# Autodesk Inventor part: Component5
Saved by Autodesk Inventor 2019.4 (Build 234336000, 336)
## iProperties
Created: 2020-06
Part Number: Component5
Material: Generic
Document SubType Name: Modeling
Designer: Administrator
Density: 1 g/cm^3
Appearance: Default
Title: Component5
Author: Administrator
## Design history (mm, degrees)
